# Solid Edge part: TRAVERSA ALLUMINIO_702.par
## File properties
Subject: TRAVERSA ALLUMINIO_702
Author: f_grande
Template: Normal.par
Last saved by: Francesco
Revision: 13
Application: Solid Edge
Material: Alluminio, 1060
Stile della faccia: Alluminio
Stile di riempimento: ANSI38(Alluminio)
Stile virtuale: Alluminio lucidato
Coef. of Thermal Exp: 0.0
Thermal Conductivity: 221.0
Specific Heat: 920.0
Modulus of Elasticity: 68947570000.0
Poisson's Ratio: 0.33
Yield Stress: 27579028.0
Ultimate Stress: 68947570.0
Elongation: 0.0
Tipo di contenuto documento: 0
Densità: 2712,000 kg/m^3
Precisione: 0,990
Document Number: KR0117
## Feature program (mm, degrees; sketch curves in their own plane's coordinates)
sketch for "unnamed Protrusion 1" #1 plane through (0, 0, 0) normal (0, -1, 0) x-axis (1, 0, 0)
  line (2.4, -2.4) -> (13.3, -2.4)
  line (13.3, -2.4) -> (13.3, -13.3)
  line (13.3, -13.3) -> (2.4, -13.3)
  line (2.4, -13.3) -> (2.4, -2.4)
sketch for "unnamed Protrusion 1" #2 plane through (0, 0, 0) normal (0, -1, 0) x-axis (1, 0, 0)
  line (18.3, 0) -> (18.3, -4.5)
  line (18.3, -4.5) -> (15.7, -4.5)
  line (15.7, -4.5) -> (15.7, -12.8)
  arc centre (18.7, -12.8) radius 3 from (18.7, -15.8) to (15.7, -12.8) cw
  line (18.7, -15.8) -> (22.5, -15.8)
  line (22.5, -15.8) -> (22.5, -19.05)
  line (22.5, -26.05) -> (22.5, -33.2)
  line (14.5, -33.2) -> (22.5, -33.2)
  line (14.5, -34.2) -> (14.5, -33.2)
  line (2.4, -34.2) -> (14.5, -34.2)
  line (2.4, -47.5) -> (2.4, -34.2)
  line (0, -47.5) -> (2.4, -47.5)
  line (0, -26.8) -> (0, -47.5)
  line (0, -26.8) -> (4.7588, -26.8)
  line (4.7588, -26.8) -> (4.7588, -29.0094)
  line (4.7588, -29.0094) -> (12.8, -29.0094)
  arc centre (12.8, -26.0094) radius 3 from (12.8, -29.0094) to (15.8, -26.0094) ccw
  line (15.8, -18.7) -> (15.8, -26.0094)
  arc centre (12.8, -18.7) radius 3 from (12.8, -15.7) to (15.8, -18.7) cw
  line (4.5, -15.7) -> (12.8, -15.7)
  line (4.5, -18.3) -> (4.5, -15.7)
  line (0, -18.3) -> (4.5, -18.3)
  line (0, -2.4) -> (0, -18.3)
  arc centre (2.4, -2.4) radius 2.4 from (2.4, 0) to (0, -2.4) ccw
  line (2.4, 0) -> (18.3, 0)
  dimension (linear) = 18.3
  dimension (linear) = 18.3
  dimension (linear) = 4.5
  dimension (linear) = 18.7
  dimension (linear) = 2.4
  dimension (linear) = 15.7
  dimension (linear) = 4.7588
  dimension (linear) = 4.7588
  dimension (linear) = 15.8
  dimension (linear) = 2.4
  dimension (linear) = 2.4
  dimension (linear) = 2.4
  dimension (linear) = 2.4
  dimension (linear) = 14.5
  dimension (linear) = 14.5
  dimension (linear) = 22.5
  dimension (linear) = 22.5
extrude "unnamed Protrusion 1" add finite 702 along -normal
body pattern "unnamed BodyPattern 1"
pattern "unnamed Pattern 1"
body pattern "unnamed BodyPattern 2"
pattern "unnamed Pattern 2"
thread "unnamed Thread 1"
thread "unnamed Thread 2"
sketch for "Foro_1" plane through (10.35, 351, -95) normal (0, 0, -1) x-axis (0, 1, 0)
hole "Foro_1" diameter 5 through
sketch for "unnamed Hole 1" plane through (10.35, 351, -95) normal (0, 0, -1) x-axis (0, 1, 0)
  hole centre (-150, -2.85) bore radius 2.5
hole "unnamed Hole 1" through
sketch for "unnamed Hole 2" plane through (10.35, 351, -95) normal (0, 0, -1) x-axis (0, 1, 0)
  hole centre (0, -2.85) bore radius 2.5
hole "unnamed Hole 2" through
sketch for "unnamed Hole 3" plane through (10.35, 351, -95) normal (0, 0, -1) x-axis (0, 1, 0)
  hole centre (150, -2.85) bore radius 2.5
hole "unnamed Hole 3" through
sketch for "unnamed Hole 4" plane through (10.35, 351, -95) normal (0, 0, -1) x-axis (0, 1, 0)
  hole centre (-300, -2.85) bore radius 2.5
  dimension (linear) = 300
hole "unnamed Hole 4" through
pattern "unnamed Pattern 3" of "Foro_1", "unnamed Hole 1", "unnamed Hole 2", "unnamed Hole 3", "unnamed Hole 4"
mirror "unnamed Mirror 1" of "unnamed Pattern 3"
pattern "unnamed Pattern 4"
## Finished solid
Body 1: solid body, 160 faces, 412 edges, 192 vertices.
  Faces by surface: plane 82, cylinder 78
  Edges by curve: line 256, circle 156
Bounding box of the edges (mm): 45.000 x 702.000 x 95.000, from (0, 0, -95) to (45, 702, 0).
Cylindrical faces by radius (mm): R2.4 x4, R2.5 x60, R3 x12, R3.5 x2
Planar faces by outward normal: +x 20, +y 1, +z 20, -x 20, -y 1, -z 20
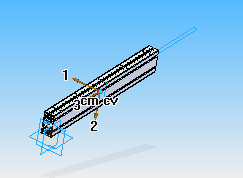
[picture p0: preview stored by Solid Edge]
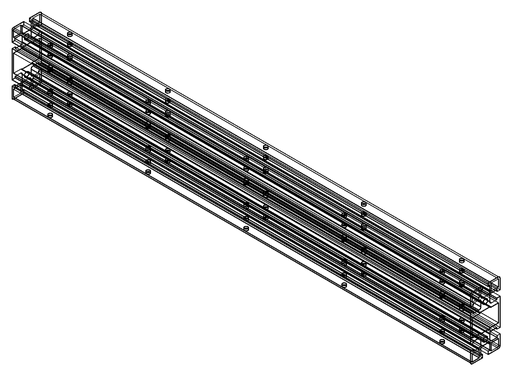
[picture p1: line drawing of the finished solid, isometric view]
